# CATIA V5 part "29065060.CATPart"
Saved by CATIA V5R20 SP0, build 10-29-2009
Part number: 29065060
Definition: NONE
Nomenclature: 29065060
Source: Unknown
Description: 29065060
Bounding box of the stored display mesh (mm): x -30 to 44.548, y -46.5 to 81.048, z -36.5 to 36.5
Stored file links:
  C:\Users\Utente\Desktop\IO LAVORO\3D X SITO CF\X SITO\PLASTICA\RF1\29065060.CATPart
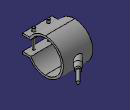
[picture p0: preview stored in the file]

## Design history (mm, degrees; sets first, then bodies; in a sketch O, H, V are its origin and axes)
Body1 "29065060" (main body)
  Solid1: solid without history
